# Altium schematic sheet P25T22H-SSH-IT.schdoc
size 127 x 101 mm
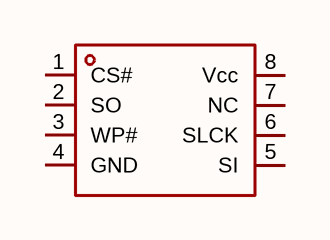
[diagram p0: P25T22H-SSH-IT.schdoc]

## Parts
U?  p25t22h-ssh-it  [SOP-8_L4.9-W3.9-P1.27-LS6.0-BL-1]  (value not drawn)

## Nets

Not connected (* = marked no-connect by the designer): U? 1(CS#) 2(SO) 3(WP#) 4(GND) 5(SI) 6(SLCK) 7(NC) 8(Vcc)

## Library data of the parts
U? = p25t22h-ssh-it: 接口类型:SPI;存储容量:2Mbit;时钟频率(fc):104MHz;; Manufacturer: PUYA(普冉); AddInBom: yes; ModelId: 75c24a7891ee4dd6bdac16a7163ff87e; ModelTransform: 192.913,236.22,0,0,0,0,0,0,0; Interface: SPI; Memory Size: 2Mbit; Clock Frequency: 104MHz; Voltage - Supply: 2.3V~3.6V; Standby Supply Current: 12uA; Program / Erase Cycles: 100000次; Page Programming Time (Tpp): 2ms; Block Erase Time(tBE): 20ms; Data Retention - TDR (Year): 20年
